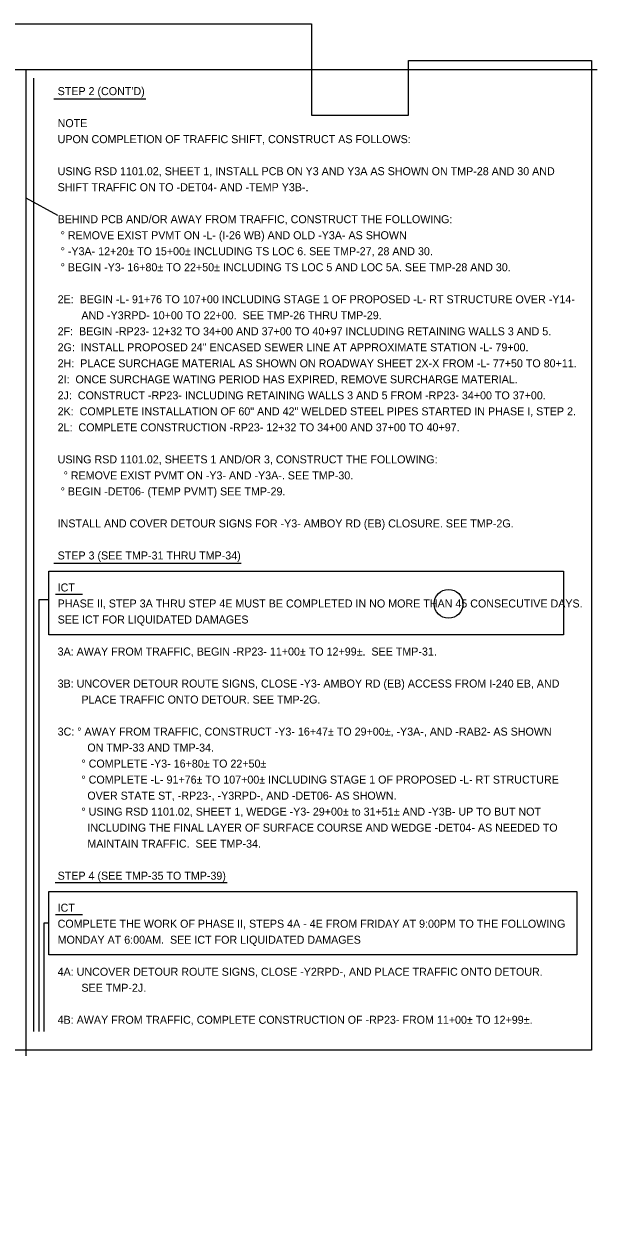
# Model space of a CAD drawing. Extents: x 2483905 to 2494512, y 366160 to 372330.
# Drawn here: x 2490010 to 2490512, y 370218 to 371258 of the extents above; entities that cross this region are included whole.
import ezdxf

# ---------------------------------------------------------------- set-up
doc = ezdxf.new("R2010")
doc.units = 0
for name, color, linetype in [('Scratch_Level_6', 7, 'Continuous'), ('TC SHEET BORDER LINE THIN', 7, 'Continuous'), ('TC SHEET LAYOUT SHAPE', 7, 'Continuous')]:
    doc.layers.add(name, color=color, linetype=linetype)

msp = doc.modelspace()

# ---------------------------------------------------------------- linework, layer by layer
at = {"layer": 'Scratch_Level_6'}
msp.add_line((2490011.6, 371106), (2490039.5, 371090.9), dxfattribs=at)
msp.add_circle((2490381.5, 370751.1), 12.6, dxfattribs=at)
at = {"layer": 'TC SHEET BORDER LINE THIN'}
for p, q in [((2490511.6, 371218), (2489011.6, 371218)), ((2490011.6, 371218), (2490011.6, 370355.9)), ((2490036.2, 371192.6), (2490116.7, 371192.6)), ((2490036.2, 370786.6), (2490200, 370786.6)), ((2490037.7, 370759.5), (2490061.3, 370759.5)), ((2490037.3, 370507.4), (2490187.7, 370507.4)), ((2490037.7, 370479.5), (2490061.3, 370479.5))]:
    msp.add_line(p, q, dxfattribs=at)
for points in [[(2490018.5, 371210.6), (2490018.5, 370377.1)], [(2490031.8, 370754.7), (2490023, 370754.7), (2490023, 370377.1)], [(2490031.8, 370471.9), (2490027.4, 370471.9), (2490027.4, 370377.1)]]:
    msp.add_lwpolyline(points, dxfattribs=at)
for points in [[(2490031.8, 370779.7), (2490482.2, 370779.7), (2490482.2, 370724.1), (2490031.8, 370724.1)], [(2490031.8, 370499.7), (2490493.7, 370499.7), (2490493.7, 370444.1), (2490031.8, 370444.1)]]:
    msp.add_lwpolyline(points, close=True, dxfattribs=at)
at = {"layer": 'TC SHEET LAYOUT SHAPE'}
msp.add_lwpolyline([(2489016.6, 370666.8), (2489016.6, 370976.2), (2489016.6, 371248.3), (2489026.6, 371258.3), (2489469.6, 371258.3), (2489940.6, 371258.3), (2490261.6, 371258.3), (2490261.6, 371178.3), (2490346.6, 371178.3), (2490346.6, 371226.3), (2490506.6, 371226.3), (2490506.6, 370891.3), (2490506.6, 370612.1), (2490506.6, 370360.8), (2489778.4, 370360.8), (2489778.4, 370218.3), (2489608.9, 370218.3), (2489256.1, 370218.3), (2489016.6, 370218.3)], close=True, dxfattribs=at)

# ---------------------------------------------------------------- texts
at = {"layer": 'TC SHEET BORDER LINE THIN'}
for s, p in [("STEP 2 (CONT'D)", (2490039.5, 371195.9)), ('NOTE', (2490039.5, 371167.9)), ('UPON COMPLETION OF TRAFFIC SHIFT, CONSTRUCT AS FOLLOWS:', (2490039.5, 371153.9)), ('USING RSD 1101.02, SHEET 1, INSTALL PCB ON Y3 AND Y3A AS SHOWN ON TMP-28 AND 30 AND', (2490039.5, 371125.9)), ('SHIFT TRAFFIC ON TO -DET04- AND -TEMP Y3B-.', (2490039.5, 371111.9)), ('BEHIND PCB AND/OR AWAY FROM TRAFFIC, CONSTRUCT THE FOLLOWING:', (2490039.5, 371083.9)), (' ° REMOVE EXIST PVMT ON -L- (I-26 WB) AND OLD -Y3A- AS SHOWN', (2490039.5, 371069.9)), (' ° -Y3A- 12+20± TO 15+00± INCLUDING TS LOC 6. SEE TMP-27, 28 AND 30.', (2490039.5, 371055.9)), (' ° BEGIN -Y3- 16+80± TO 22+50± INCLUDING TS LOC 5 AND LOC 5A. SEE TMP-28 AND 30.', (2490039.5, 371041.9)), ('2E:  BEGIN -L- 91+76 TO 107+00 INCLUDING STAGE 1 OF PROPOSED -L- RT STRUCTURE OVER -Y14-', (2490039.5, 371013.9)), ('        AND -Y3RPD- 10+00 TO 22+00.  SEE TMP-26 THRU TMP-29.', (2490039.5, 370999.9)), ('2F:  BEGIN -RP23- 12+32 TO 34+00 AND 37+00 TO 40+97 INCLUDING RETAINING WALLS 3 AND 5.', (2490039.5, 370985.9)), ('2G:  INSTALL PROPOSED 24" ENCASED SEWER LINE AT APPROXIMATE STATION -L- 79+00.', (2490039.5, 370971.9)), ('2H:  PLACE SURCHAGE MATERIAL AS SHOWN ON ROADWAY SHEET 2X-X FROM -L- 77+50 TO 80+11.', (2490039.5, 370957.9)), ('2I:  ONCE SURCHAGE WATING PERIOD HAS EXPIRED, REMOVE SURCHARGE MATERIAL.', (2490039.5, 370943.9)), ('2J:  CONSTRUCT -RP23- INCLUDING RETAINING WALLS 3 AND 5 FROM -RP23- 34+00 TO 37+00.', (2490039.5, 370929.9)), ('2K:  COMPLETE INSTALLATION OF 60" AND 42" WELDED STEEL PIPES STARTED IN PHASE I, STEP 2.', (2490039.5, 370915.9)), ('2L:  COMPLETE CONSTRUCTION -RP23- 12+32 TO 34+00 AND 37+00 TO 40+97.  ', (2490039.5, 370901.9)), ('USING RSD 1101.02, SHEETS 1 AND/OR 3, CONSTRUCT THE FOLLOWING:', (2490039.5, 370873.9)), ('  ° REMOVE EXIST PVMT ON -Y3- AND -Y3A-. SEE TMP-30.', (2490039.5, 370859.9)), (' ° BEGIN -DET06- (TEMP PVMT) SEE TMP-29.', (2490039.5, 370845.9)), ('INSTALL AND COVER DETOUR SIGNS FOR -Y3- AMBOY RD (EB) CLOSURE. SEE TMP-2G.', (2490039.5, 370817.9)), ('STEP 3 (SEE TMP-31 THRU TMP-34)', (2490039.5, 370789.9)), ('ICT', (2490039.5, 370761.9)), ('PHASE II, STEP 3A THRU STEP 4E MUST BE COMPLETED IN NO MORE THAN 45 CONSECUTIVE DAYS.', (2490039.5, 370747.9)), ('SEE ICT FOR LIQUIDATED DAMAGES', (2490039.5, 370733.9)), ('3A: AWAY FROM TRAFFIC, BEGIN -RP23- 11+00± TO 12+99±.  SEE TMP-31.', (2490039.5, 370705.9)), ('3B: UNCOVER DETOUR ROUTE SIGNS, CLOSE -Y3- AMBOY RD (EB) ACCESS FROM I-240 EB, AND', (2490039.5, 370677.9)), ('        PLACE TRAFFIC ONTO DETOUR. SEE TMP-2G.', (2490039.5, 370663.9)), ('3C: ° AWAY FROM TRAFFIC, CONSTRUCT -Y3- 16+47± TO 29+00±, -Y3A-, AND -RAB2- AS SHOWN', (2490039.5, 370635.9)), ('          ON TMP-33 AND TMP-34.', (2490039.5, 370621.9)), ('        ° COMPLETE -Y3- 16+80± TO 22+50±', (2490039.5, 370607.9)), ('        ° COMPLETE -L- 91+76± TO 107+00± INCLUDING STAGE 1 OF PROPOSED -L- RT STRUCTURE', (2490039.5, 370593.9)), ('          OVER STATE ST, -RP23-, -Y3RPD-, AND -DET06- AS SHOWN.', (2490039.5, 370579.9)), ('        ° USING RSD 1101.02, SHEET 1, WEDGE -Y3- 29+00± to 31+51± AND -Y3B- UP TO BUT NOT', (2490039.5, 370565.9)), ('          INCLUDING THE FINAL LAYER OF SURFACE COURSE AND WEDGE -DET04- AS NEEDED TO', (2490039.5, 370551.9)), ('          MAINTAIN TRAFFIC.  SEE TMP-34.', (2490039.5, 370537.9)), ('STEP 4 (SEE TMP-35 TO TMP-39)', (2490039.5, 370509.9)), ('ICT', (2490039.5, 370481.9)), ('COMPLETE THE WORK OF PHASE II, STEPS 4A - 4E FROM FRIDAY AT 9:00PM TO THE FOLLOWING', (2490039.5, 370467.9)), ('MONDAY AT 6:00AM.  SEE ICT FOR LIQUIDATED DAMAGES', (2490039.5, 370453.9)), ('4A: UNCOVER DETOUR ROUTE SIGNS, CLOSE -Y2RPD-, AND PLACE TRAFFIC ONTO DETOUR.', (2490039.5, 370425.9)), ('        SEE TMP-2J.', (2490039.5, 370411.9)), ('4B: AWAY FROM TRAFFIC, COMPLETE CONSTRUCTION OF -RP23- FROM 11+00± TO 12+99±.', (2490039.5, 370383.9))]:
    msp.add_text(s, height=7, dxfattribs=at).set_placement(p)

doc.saveas('drawing.dxf')
